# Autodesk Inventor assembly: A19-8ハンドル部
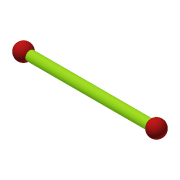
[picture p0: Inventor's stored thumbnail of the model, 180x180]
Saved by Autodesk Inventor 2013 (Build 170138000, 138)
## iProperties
Created: 2008-07
Part Number: A19-8ハンドル部
Document SubType Name: Assembly
Designer: y-shimohigashi
Stock Number: A19-8ハンドル部
Author: y-shimohigashi
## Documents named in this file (3)
- C:\Users\t-komatsu\Desktop\新しいフォルダー\Inventor2013基礎コース\練習問題-19\A19-8ハンドル部.iam
- C:\Users\t-komatsu\Desktop\新しいフォルダー\Inventor2013基礎コース\練習問題-19\P19-9ハンドル.ipt
- C:\Users\t-komatsu\Desktop\新しいフォルダー\Inventor2013基礎コース\練習問題-19\P19-10ボス.ipt
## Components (3 placed, 2 different names)
1. P19-9ハンドル:1 — 挿入:1, 挿入:2
2. P19-10ボス:1 — 挿入:1
3. P19-10ボス:2 — 挿入:2
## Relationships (2: Insert 2)
- 挿入:1 [Insert]: P19-9ハンドル:1 ↔ P19-10ボス:1
- 挿入:2 [Insert]: P19-9ハンドル:1 ↔ P19-10ボス:2
